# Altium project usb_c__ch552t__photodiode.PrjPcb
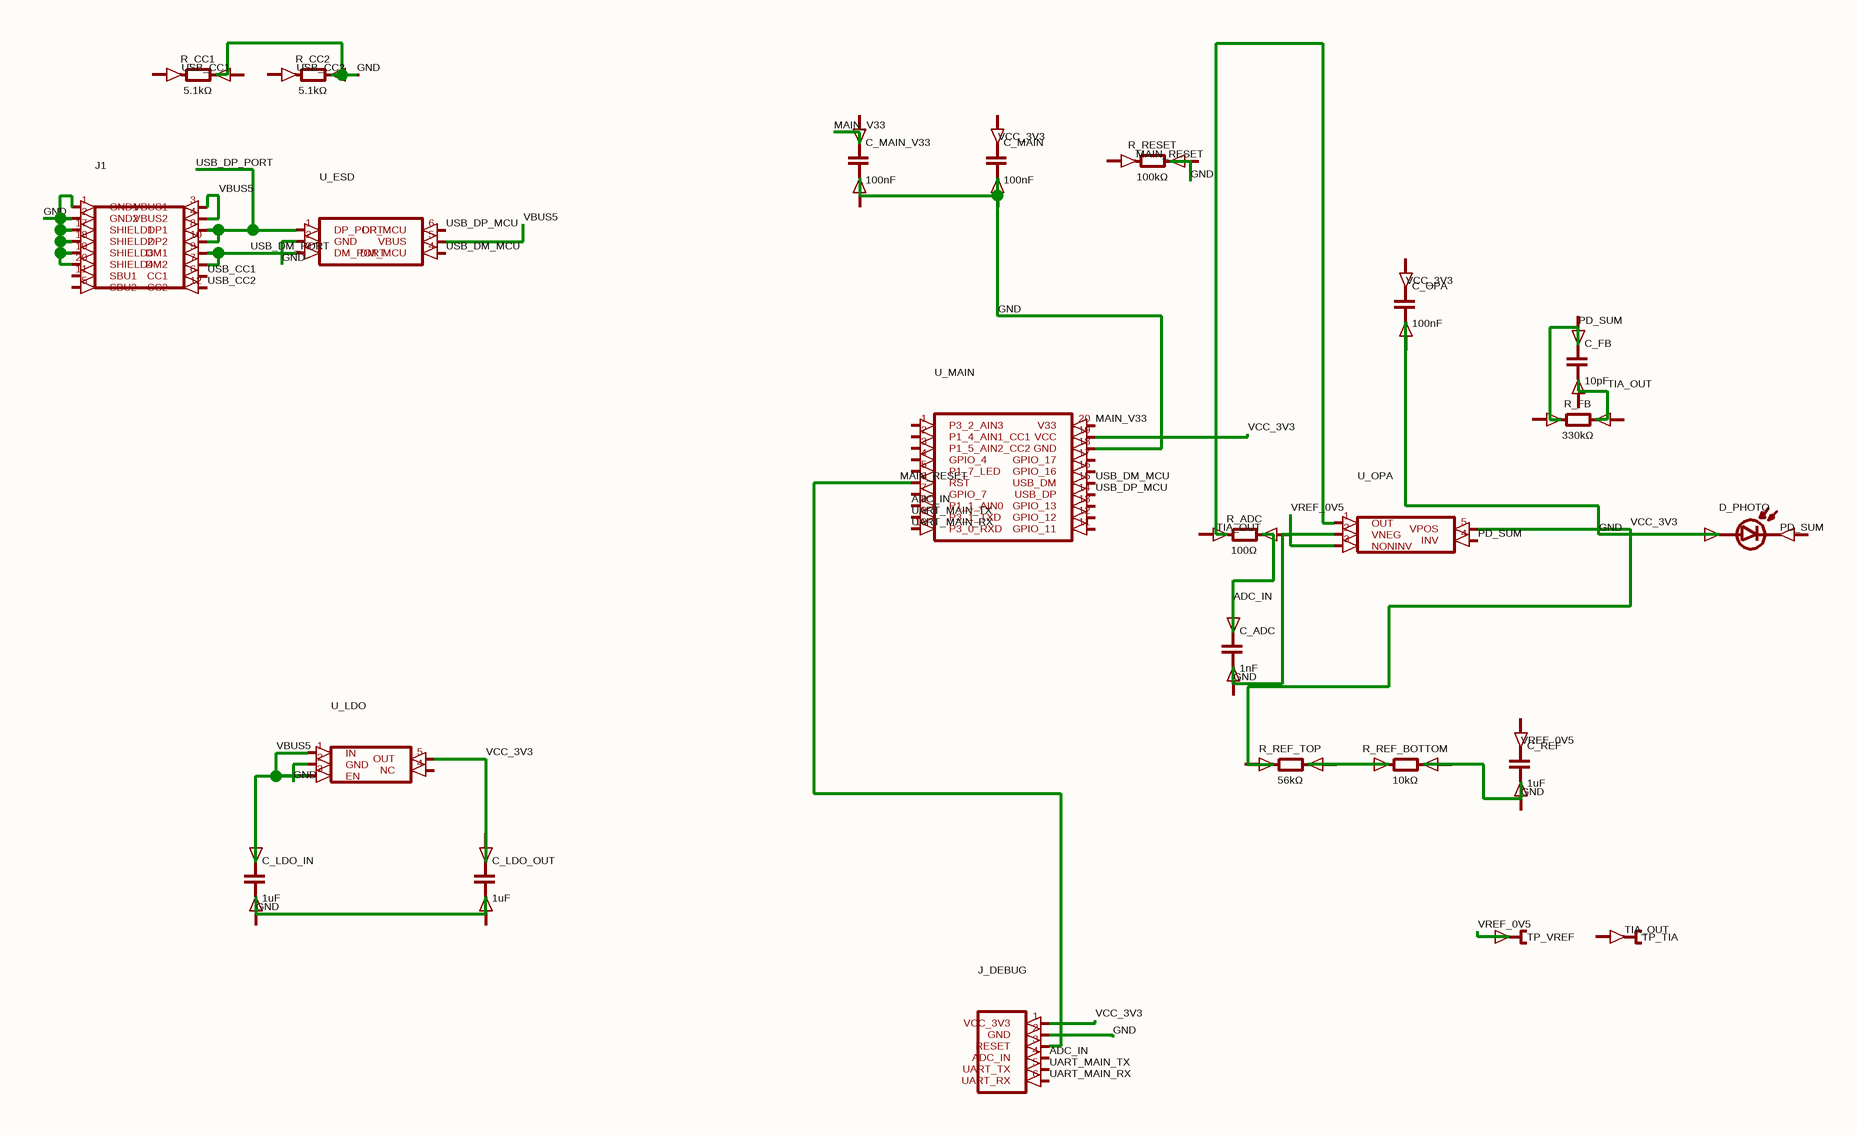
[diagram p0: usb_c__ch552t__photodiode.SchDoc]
1 sheet, 24 parts. Net scope: global (net labels, ports and power ports of the same name join across sheets).
Board file: usb_c__ch552t__photodiode.PcbDoc

## Sheet usb_c__ch552t__photodiode.SchDoc
size 206 x 142 mm

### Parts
C_ADC  1nF
C_FB  10pF
C_LDO_IN  1uF
C_LDO_OUT  1uF
C_MAIN  100nF
C_MAIN_V33  100nF
C_OPA  100nF
C_REF  1uF
D_PHOTO  (no value)
J1  (no value)
J_DEBUG  (no value)
R_ADC  100Ω
R_CC1  5.1kΩ
R_CC2  5.1kΩ
R_FB  330kΩ
R_REF_BOTTOM  10kΩ
R_REF_TOP  56kΩ
R_RESET  100kΩ
TP_TIA  (no value)
TP_VREF  (no value)
U_ESD  (no value)
U_LDO  (no value)
U_MAIN  (no value)
U_OPA  (no value)

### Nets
ADC_IN: C_ADC.1(anode) J_DEBUG.4(ADC_IN) U_MAIN.8(P1_1_AIN0)
GND: C_LDO_IN.1(anode) C_LDO_OUT.1(anode) C_MAIN.2(cathode) C_OPA.2(cathode) D_PHOTO.1(anode) J1.1(GND1) J1.2(GND2) J1.3(VBUS1) J1.4(VBUS2) J1.7(DM2) J1.9(DM1) J1.17(SHIELD1) J1.18(SHIELD2) J1.19(SHIELD3) J1.20(SHIELD4) J_DEBUG.1(VCC_3V3) J_DEBUG.2(GND) R_ADC.2(cathode) R_REF_BOTTOM.2(cathode) TP_VREF.1(pin1) U_ESD.2(GND) U_ESD.3(DM_PORT) U_ESD.5(VBUS) U_LDO.1(IN) U_LDO.2(GND) U_LDO.3(EN) U_LDO.5(OUT) U_MAIN.18(GND) U_MAIN.19(VCC) U_OPA.1(OUT) U_OPA.2(VNEG) U_OPA.3(NONINV) U_OPA.5(VPOS)  [also labelled TIA_OUT, USB_DM_PORT, VBUS5, VCC_3V3, VREF_0V5]
MAIN_RESET: J_DEBUG.3(RESET) U_MAIN.6(RST)
MAIN_V33: U_MAIN.20(V33)
PD_SUM: U_OPA.4(INV)
UART_MAIN_RX: J_DEBUG.6(UART_RX) U_MAIN.10(P3_0_RXD)
UART_MAIN_TX: J_DEBUG.5(UART_TX) U_MAIN.9(P3_1_TXD)
USB_CC1: J1.6(CC1)
USB_CC2: J1.12(CC2)
USB_DM_MCU: U_ESD.4(DM_MCU) U_MAIN.15(USB_DM)
USB_DP_MCU: U_ESD.6(DP_MCU) U_MAIN.14(USB_DP)
USB_DP_PORT: J1.8(DP1) J1.10(DP2) U_ESD.1(DP_PORT)
NetR_REF_BOTTOM_1: R_REF_BOTTOM.1(anode) R_REF_TOP.2(cathode)

Not connected (* = marked no-connect by the designer): C_ADC 2(cathode); C_FB 1(anode) 2(cathode); C_LDO_IN 2(cathode); C_LDO_OUT 2(cathode); C_MAIN 1(anode); C_MAIN_V33 1(anode) 2(cathode); C_OPA 1(anode); C_REF 1(anode) 2(cathode); D_PHOTO 2(cathode); J1 5(SBU2) 11(SBU1); R_ADC 1(anode); R_CC1 1(anode) 2(cathode); R_CC2 1(anode) 2(cathode); R_FB 1(anode) 2(cathode); R_REF_TOP 1(anode); R_RESET 1(anode) 2(cathode); TP_TIA 1(pin1); U_LDO 4(NC); U_MAIN 1(P3_2_AIN3) 2(P1_4_AIN1_CC1) 3(P1_5_AIN2_CC2) 4(GPIO_4) 5(P1_7_LED) 7(GPIO_7) 11(GPIO_11) 12(GPIO_12) 13(GPIO_13) 16(GPIO_16) 17(GPIO_17)

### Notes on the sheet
- Labels drawn without touching a wire or pin: MAIN_RESET, PD_SUM, TIA_OUT, USB_CC1, USB_CC2, VCC_3V3, VREF_0V5

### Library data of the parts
C_ADC C_FB C_LDO_IN C_LDO_OUT C_MAIN C_MAIN_V33 C_OPA C_REF = capacitor_down
D_PHOTO = photodiode_horz
J1 = J1
J_DEBUG = J_DEBUG
R_ADC R_CC1 R_CC2 R_FB R_REF_BOTTOM R_REF_TOP R_RESET = boxresistor_right
TP_TIA TP_VREF = testpoint_right
U_ESD = U_ESD
U_LDO = U_LDO
U_MAIN = U_MAIN
U_OPA = U_OPA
